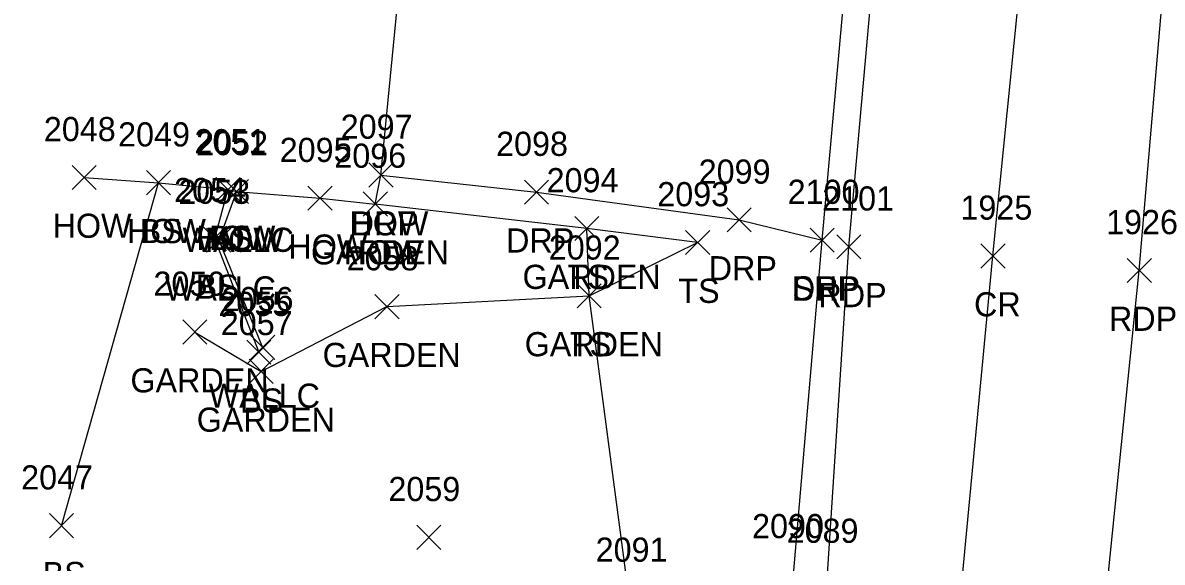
# Model space of a CAD drawing. Extents: x 1653908 to 1654393, y 539913 to 544256.
# Drawn here: x 1654002.8 to 1654097.1, y 541769.8 to 541814.4 of the extents above; entities that cross this region are included whole.
import ezdxf

# ---------------------------------------------------------------- set-up
doc = ezdxf.new("R2010")
doc.units = 0
for name, color, linetype in [('L_A', 7, 'Continuous'), ('L_I', 7, 'Continuous'), ('L_TIC', 7, 'Continuous'), ('LAPB', 7, 'Continuous'), ('LBC', 7, 'Continuous'), ('LELB', 7, 'Continuous'), ('LW', 7, 'Continuous'), ('P_A', 7, 'Continuous'), ('P_I', 7, 'Continuous'), ('P_TIC', 7, 'Continuous'), ('PET', 7, 'Continuous'), ('PRC', 7, 'Continuous'), ('PSP', 7, 'Continuous'), ('R_A', 7, 'Continuous'), ('R_I', 7, 'Continuous'), ('R_TIC', 7, 'Continuous'), ('RDP', 7, 'Continuous')]:
    doc.layers.add(name, color=color, linetype=linetype)

msp = doc.modelspace()

# ---------------------------------------------------------------- linework, layer by layer
at = {"layer": 'L_TIC'}
for points in [[(1654006.873, 541800.62), (1654008.873, 541802.62)], [(1654008.873, 541800.62), (1654006.873, 541802.62)], [(1654013.029, 541800.181), (1654015.029, 541802.181)], [(1654015.029, 541800.181), (1654013.029, 541802.181)], [(1654013.029, 541800.181), (1654015.029, 541802.181)], [(1654015.029, 541800.181), (1654013.029, 541802.181)], [(1654031.451, 541800.82), (1654033.451, 541802.82)], [(1654033.451, 541800.82), (1654031.451, 541802.82)], [(1654018.778, 541799.618), (1654020.778, 541801.618)], [(1654020.778, 541799.618), (1654018.778, 541801.618)], [(1654018.778, 541799.618), (1654020.778, 541801.618)], [(1654020.778, 541799.618), (1654018.778, 541801.618)], [(1654019.485, 541799.459), (1654021.485, 541801.459)], [(1654021.485, 541799.459), (1654019.485, 541801.459)], [(1654019.485, 541799.459), (1654021.485, 541801.459)], [(1654021.485, 541799.459), (1654019.485, 541801.459)], [(1654026.402, 541798.898), (1654028.402, 541800.898)], [(1654028.402, 541798.898), (1654026.402, 541800.898)], [(1654030.981, 541798.418), (1654032.981, 541800.418)], [(1654032.981, 541798.418), (1654030.981, 541800.418)], [(1654030.981, 541798.418), (1654032.981, 541800.418)], [(1654032.981, 541798.418), (1654030.981, 541800.418)], [(1654048.503, 541796.391), (1654050.503, 541798.391)], [(1654050.503, 541796.391), (1654048.503, 541798.391)], [(1654048.503, 541796.391), (1654050.503, 541798.391)], [(1654050.503, 541796.391), (1654048.503, 541798.391)], [(1654017.658, 541795.578), (1654019.658, 541797.578)], [(1654019.658, 541795.578), (1654017.658, 541797.578)], [(1654018.01, 541795.433), (1654020.01, 541797.433)], [(1654020.01, 541795.433), (1654018.01, 541797.433)], [(1654057.668, 541795.234), (1654059.668, 541797.234)], [(1654059.668, 541795.234), (1654057.668, 541797.234)], [(1654048.682, 541790.817), (1654050.682, 541792.817)], [(1654050.682, 541790.817), (1654048.682, 541792.817)], [(1654048.682, 541790.817), (1654050.682, 541792.817)], [(1654050.682, 541790.817), (1654048.682, 541792.817)], [(1654031.946, 541789.929), (1654033.946, 541791.929)], [(1654033.946, 541789.929), (1654031.946, 541791.929)], [(1654016.034, 541787.825), (1654018.034, 541789.825)], [(1654018.034, 541787.825), (1654016.034, 541789.825)], [(1654021.334, 541786.151), (1654023.334, 541788.151)], [(1654023.334, 541786.151), (1654021.334, 541788.151)], [(1654021.648, 541786.552), (1654023.648, 541788.552)], [(1654023.648, 541786.552), (1654021.648, 541788.552)], [(1654021.523, 541784.569), (1654023.523, 541786.569)], [(1654023.523, 541784.569), (1654021.523, 541786.569)], [(1654004.993, 541771.793), (1654006.993, 541773.793)], [(1654006.993, 541771.793), (1654004.993, 541773.793)], [(1654035.412, 541770.831), (1654037.412, 541772.831)], [(1654037.412, 541770.831), (1654035.412, 541772.831)]]:
    msp.add_lwpolyline(points, dxfattribs=at)
at = {"layer": 'LAPB'}
msp.add_lwpolyline([(1654017.034, 541788.825), (1654022.523, 541785.569), (1654032.946, 541790.929), (1654049.682, 541791.817), (1654049.503, 541797.391), (1654031.981, 541799.418)], dxfattribs=at)
at = {"layer": 'LBC'}
msp.add_lwpolyline([(1654007.873, 541801.62), (1654014.029, 541801.181), (1654019.778, 541800.618), (1654020.485, 541800.459), (1654027.402, 541799.898), (1654031.981, 541799.418), (1654032.451, 541801.82), (1654034.755, 541825.55), (1654035.904, 541837.113)], dxfattribs=at)
at = {"layer": 'LELB'}
for points in [[(1654005.993, 541772.793), (1654014.029, 541801.181)], [(1654019.778, 541800.618), (1654018.658, 541796.578), (1654022.334, 541787.151)], [(1654055.348, 541690.71), (1654055.636, 541695.833), (1654055.206, 541698.7), (1654056.806, 541729.488), (1654055.917, 541739.446), (1654052.997, 541766.812), (1654049.682, 541791.817), (1654058.668, 541796.234), (1654049.503, 541797.391)]]:
    msp.add_lwpolyline(points, dxfattribs=at)
at = {"layer": 'LW'}
msp.add_lwpolyline([(1654020.485, 541800.459), (1654019.01, 541796.433), (1654022.648, 541787.552)], dxfattribs=at)
at = {"layer": 'P_TIC'}
for points in [[(1654067.984, 541795.432), (1654069.984, 541797.432)], [(1654069.984, 541795.432), (1654067.984, 541797.432)], [(1654070.189, 541794.88), (1654072.189, 541796.88)], [(1654072.189, 541794.88), (1654070.189, 541796.88)], [(1654082.127, 541794.122), (1654084.127, 541796.122)], [(1654084.127, 541794.122), (1654082.127, 541796.122)], [(1654094.245, 541792.922), (1654096.245, 541794.922)], [(1654096.245, 541792.922), (1654094.245, 541794.922)]]:
    msp.add_lwpolyline(points, dxfattribs=at)
at = {"layer": 'PET'}
for points in [[(1654079.776, 541659.551), (1654071.378, 541669.623), (1654062.104, 541680.771), (1654062.282, 541682.129), (1654062.946, 541688.197), (1654063.578, 541697.883), (1654065.97, 541728.278), (1654069.389, 541768.376), (1654071.189, 541795.88), (1654073.496, 541821.499), (1654077.02, 541859.137), (1654082.158, 541914.04), (1654084.92, 541947.882), (1654085.876, 541956.638), (1654088.374, 541984.799), (1654091.953, 542029.606), (1654095.296, 542063.753), (1654100.144, 542114.452), (1654103.127, 542154.148), (1654108.142, 542200.441), (1654110.744, 542235.382)], [(1654079.776, 541659.551), (1654080.091, 541663.585), (1654084.434, 541705.035), (1654088.467, 541726.588), (1654090.823, 541750.421), (1654095.245, 541793.922), (1654098.735, 541834.906), (1654102.668, 541873.549), (1654106.19, 541915.359), (1654108.801, 541937.78), (1654112.78, 541976.541), (1654113.712, 541994.764), (1654118.507, 542040.261), (1654122.37, 542081.456), (1654125.512, 542120.567), (1654128.858, 542154.493), (1654132.07, 542197.521), (1654136.387, 542232.744)]]:
    msp.add_lwpolyline(points, dxfattribs=at)
at = {"layer": 'PRC'}
msp.add_lwpolyline([(1654071.378, 541669.623), (1654074.689, 541707.082), (1654077.078, 541730.589), (1654080.001, 541762.219), (1654083.127, 541795.122), (1654087.252, 541836.363), (1654090.634, 541873.535), (1654094.478, 541915.806), (1654096.589, 541938.824), (1654100.212, 541977.673), (1654102.082, 541996.315), (1654106.328, 542040.19), (1654109.98, 542082.612), (1654113.749, 542122.62), (1654117.046, 542159.879), (1654120.869, 542199.278), (1654124.055, 542234.043)], dxfattribs=at)
at = {"layer": 'PSP'}
msp.add_lwpolyline([(1654059.287, 541697.924), (1654062.434, 541729.204), (1654066.607, 541768.761), (1654068.984, 541796.432), (1654071.265, 541821.837), (1654073.124, 541859.772), (1654076.966, 541914.969), (1654078.39, 541941.536)], dxfattribs=at)
at = {"layer": 'R_TIC'}
for points in [[(1654031.451, 541800.82), (1654033.451, 541802.82)], [(1654033.451, 541800.82), (1654031.451, 541802.82)], [(1654044.324, 541799.402), (1654046.324, 541801.402)], [(1654046.324, 541799.402), (1654044.324, 541801.402)], [(1654061.103, 541797.103), (1654063.103, 541799.103)], [(1654063.103, 541797.103), (1654061.103, 541799.103)], [(1654067.984, 541795.432), (1654069.984, 541797.432)], [(1654069.984, 541795.432), (1654067.984, 541797.432)]]:
    msp.add_lwpolyline(points, dxfattribs=at)
at = {"layer": 'RDP'}
msp.add_lwpolyline([(1654032.451, 541801.82), (1654045.324, 541800.402), (1654062.103, 541798.103), (1654068.984, 541796.432)], dxfattribs=at)

# ---------------------------------------------------------------- texts
at = {"layer": 'L_A'}
for s, p in [('HOW', (1654005.259, 541796.62)), ('HOW', (1654011.415, 541796.181)), ('BS', (1654012.47, 541796.181)), ('HOW', (1654029.837, 541796.82)), ('WALLC', (1654016.021, 541795.459)), ('HOW', (1654017.164, 541795.618)), ('HOW', (1654017.871, 541795.459)), ('BS', (1654018.219, 541795.618)), ('HOW', (1654024.788, 541794.898)), ('GARDEN', (1654026.65, 541794.418)), ('HOW', (1654029.367, 541794.418)), ('GARDEN', (1654044.173, 541792.391)), ('TS', (1654047.913, 541792.391)), ('WALLC', (1654014.546, 541791.433)), ('BS', (1654017.099, 541791.578)), ('TS', (1654057.077, 541791.234)), ('GARDEN', (1654044.351, 541786.817)), ('TS', (1654048.091, 541786.817)), ('GARDEN', (1654027.615, 541785.929)), ('GARDEN', (1654011.703, 541783.825)), ('WALLC', (1654018.183, 541782.552)), ('BS', (1654020.775, 541782.151)), ('GARDEN', (1654017.192, 541780.569)), ('BS', (1654004.434, 541767.793))]:
    msp.add_text(s, height=2, dxfattribs=at).set_placement(p)
at = {"layer": 'L_I'}
for s, p in [('2097', (1654029.113, 541804.82)), ('2048', (1654004.534, 541804.62)), ('2049', (1654010.683, 541804.181)), ('2049', (1654010.683, 541804.181)), ('2051', (1654017.007, 541803.618)), ('2051', (1654017.007, 541803.618)), ('2052', (1654017.147, 541803.459)), ('2052', (1654017.147, 541803.459)), ('2095', (1654024.064, 541802.898)), ('2096', (1654028.587, 541802.418)), ('2096', (1654028.587, 541802.418)), ('2094', (1654046.165, 541800.391)), ('2094', (1654046.165, 541800.391)), ('2054', (1654015.32, 541799.578)), ('2053', (1654015.672, 541799.433)), ('2093', (1654055.329, 541799.234)), ('2092', (1654046.343, 541794.817)), ('2092', (1654046.343, 541794.817)), ('2058', (1654029.607, 541793.929)), ('2050', (1654013.609, 541791.825)), ('2056', (1654019.254, 541790.552)), ('2055', (1654018.995, 541790.151)), ('2057', (1654019.184, 541788.569)), ('2047', (1654002.655, 541775.793)), ('2059', (1654033.066, 541774.831)), ('2091', (1654050.226, 541769.812))]:
    msp.add_text(s, height=2, dxfattribs=at).set_placement(p)
at = {"layer": 'P_A'}
for s, p in [('SHP', (1654066.52, 541791.432)), ('RDP', (1654068.677, 541790.88)), ('CR', (1654081.56, 541790.122)), ('RDP', (1654092.733, 541788.922))]:
    msp.add_text(s, height=2, dxfattribs=at).set_placement(p)
at = {"layer": 'P_I'}
for s, p in [('2100', (1654066.126, 541799.432)), ('2101', (1654068.984, 541798.88)), ('1925', (1654080.434, 541798.122)), ('1926', (1654092.497, 541796.922)), ('2090', (1654063.182, 541771.761)), ('2089', (1654066.043, 541771.376))]:
    msp.add_text(s, height=2, dxfattribs=at).set_placement(p)
at = {"layer": 'R_A'}
for p in [(1654029.939, 541796.82), (1654042.812, 541795.402), (1654059.591, 541793.103), (1654066.473, 541791.432)]:
    msp.add_text('DRP', height=2, dxfattribs=at).set_placement(p)
at = {"layer": 'R_I'}
for s, p in [('2097', (1654029.113, 541804.82)), ('2098', (1654041.985, 541803.402)), ('2099', (1654058.757, 541801.103)), ('2100', (1654066.126, 541799.432))]:
    msp.add_text(s, height=2, dxfattribs=at).set_placement(p)

doc.saveas('drawing.dxf')
